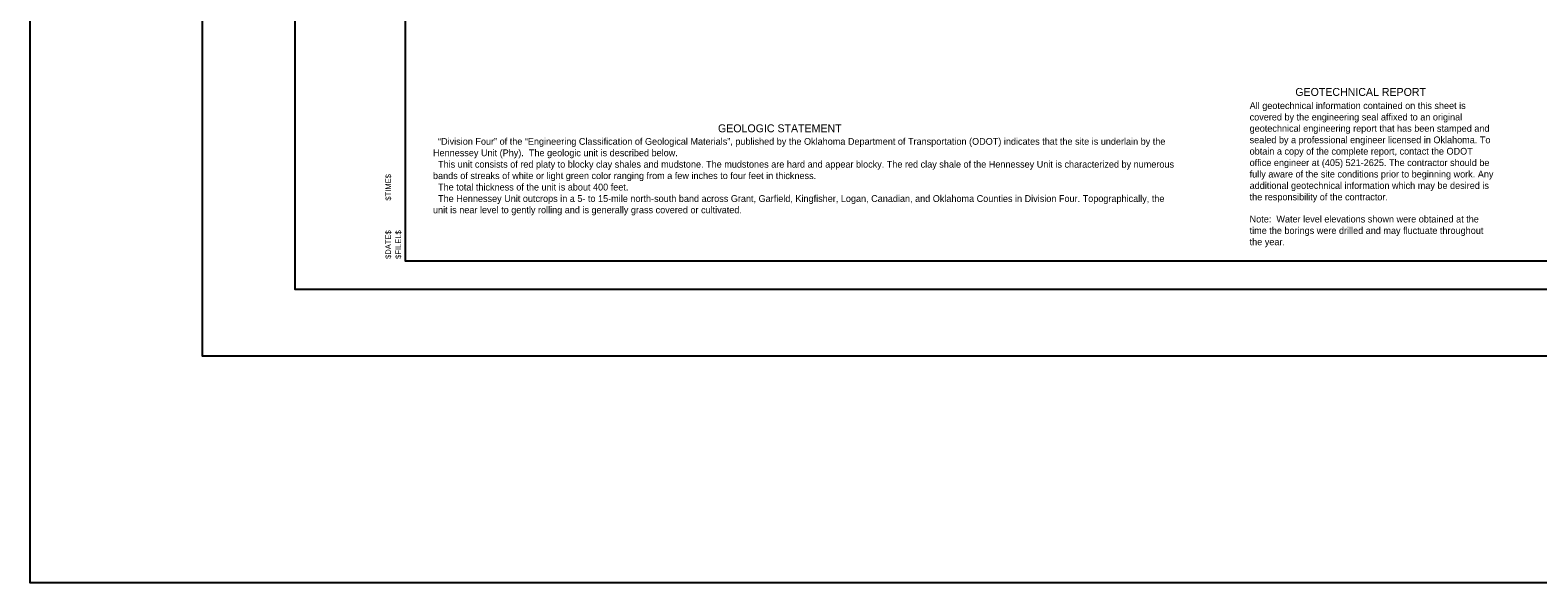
# Model space of a CAD drawing. Extents: x 2150161.5 to 2150203.1, y 143779.5 to 143868.5.
# Drawn here: x 2150161.53 to 2150188.17, y 143779.54 to 143789.3 of the extents above; entities that cross this region are included whole.
import ezdxf

# ---------------------------------------------------------------- set-up
doc = ezdxf.new("R2010")
doc.units = 0
for name, color, linetype in [('S', 7, 'Continuous'), ('SHT_Plot_Shape_Full', 7, 'Continuous'), ('SHT_Plot_Shape_Half', 7, 'Continuous'), ('SHT_Plot_Stamp', 7, 'Continuous'), ('SHT_Sheet_Border', 7, 'Continuous'), ('Text', 7, 'Continuous')]:
    doc.layers.add(name, color=color, linetype=linetype)

# ---------------------------------------------------------------- blocks, each defined once
blk = doc.blocks.new('Stamp_Plot_Stamp')
at = {"layer": 'SHT_Plot_Stamp'}
for s, p in [('$TIME$', (1.695, 1.572)), ('$DATE$', (1.695, 0.542)), ('$FILEL$', (1.873, 0.542))]:
    blk.add_text(s, height=0.1, rotation=90, dxfattribs=at).set_placement(p)

msp = doc.modelspace()

# ---------------------------------------------------------------- linework, layer by layer
at = {"layer": 'S'}
msp.add_lwpolyline([(2150161.53, 143868.477), (2150203.071, 143868.477), (2150203.071, 143779.536), (2150161.53, 143779.536)], close=True, dxfattribs=at)
at = {"layer": 'SHT_Plot_Shape_Full'}
msp.add_lwpolyline([(2150164.575, 143807.544), (2150200.575, 143807.544), (2150200.575, 143783.544), (2150164.575, 143783.544)], close=True, dxfattribs=at)
at = {"layer": 'SHT_Plot_Shape_Half'}
msp.add_lwpolyline([(2150166.212, 143806.719), (2150200.212, 143806.719), (2150200.212, 143784.719), (2150166.212, 143784.719)], close=True, dxfattribs=at)
at = {"layer": 'SHT_Sheet_Border'}
msp.add_lwpolyline([(2150199.662, 143785.219), (2150168.162, 143785.219), (2150168.162, 143806.219), (2150199.662, 143806.219)], close=True, dxfattribs=at)

# ---------------------------------------------------------------- block references
at = {"layer": 'SHT_Plot_Stamp'}
msp.add_blockref('Stamp_Plot_Stamp', (2150166.212, 143784.719), dxfattribs=at)

# ---------------------------------------------------------------- texts
at = {"layer": 'Text'}
for s, height, p in [('GEOTECHNICAL REPORT', 0.14, (2150183.885, 143788.142)), ('All geotechnical information contained on this sheet is ', 0.12, (2150183.078, 143787.91)), ('GEOLOGIC STATEMENT', 0.14, (2150173.684, 143787.499)), ('covered by the engineering seal affixed to an original ', 0.12, (2150183.078, 143787.708)), ('geotechnical engineering report that has been stamped and ', 0.12, (2150183.078, 143787.508)), ('  “Division Four” of the “Engineering Classification of Geological Materials”, published by the Oklahoma Department of Transportation (ODOT) indicates that the site is underlain by the ', 0.12, (2150168.648, 143787.278)), ('sealed by a professional engineer licensed in Oklahoma. To ', 0.12, (2150183.078, 143787.306)), ('Hennessey Unit (Phy).  The geologic unit is described below. ', 0.12, (2150168.648, 143787.076)), ('obtain a copy of the complete report, contact the ODOT ', 0.12, (2150183.078, 143787.104)), ('bands of streaks of white or light green color ranging from a few inches to four feet in thickness. ', 0.12, (2150168.648, 143786.672)), ('  This unit consists of red platy to blocky clay shales and mudstone. The mudstones are hard and appear blocky. The red clay shale of the Hennessey Unit is characterized by numerous ', 0.12, (2150168.648, 143786.874)), ('fully aware of the site conditions prior to beginning work. Any ', 0.12, (2150183.078, 143786.7)), ('office engineer at (405) 521-2625. The contractor should be ', 0.12, (2150183.078, 143786.902)), ('  The total thickness of the unit is about 400 feet.', 0.12, (2150168.648, 143786.47)), ('additional geotechnical information which may be desired is ', 0.12, (2150183.078, 143786.498)), ('  The Hennessey Unit outcrops in a 5- to 15-mile north-south band across Grant, Garfield, Kingfisher, Logan, Canadian, and Oklahoma Counties in Division Four. Topographically, the ', 0.12, (2150168.648, 143786.268)), ('the responsibility of the contractor.', 0.12, (2150183.078, 143786.296)), ('unit is near level to gently rolling and is generally grass covered or cultivated.', 0.12, (2150168.648, 143786.068)), ('Note:  Water level elevations shown were obtained at the ', 0.12, (2150183.078, 143785.905)), ('time the borings were drilled and may fluctuate throughout ', 0.12, (2150183.078, 143785.703)), ('the year.', 0.12, (2150183.078, 143785.503))]:
    msp.add_text(s, height=height, dxfattribs=at).set_placement(p)

doc.saveas('drawing.dxf')
